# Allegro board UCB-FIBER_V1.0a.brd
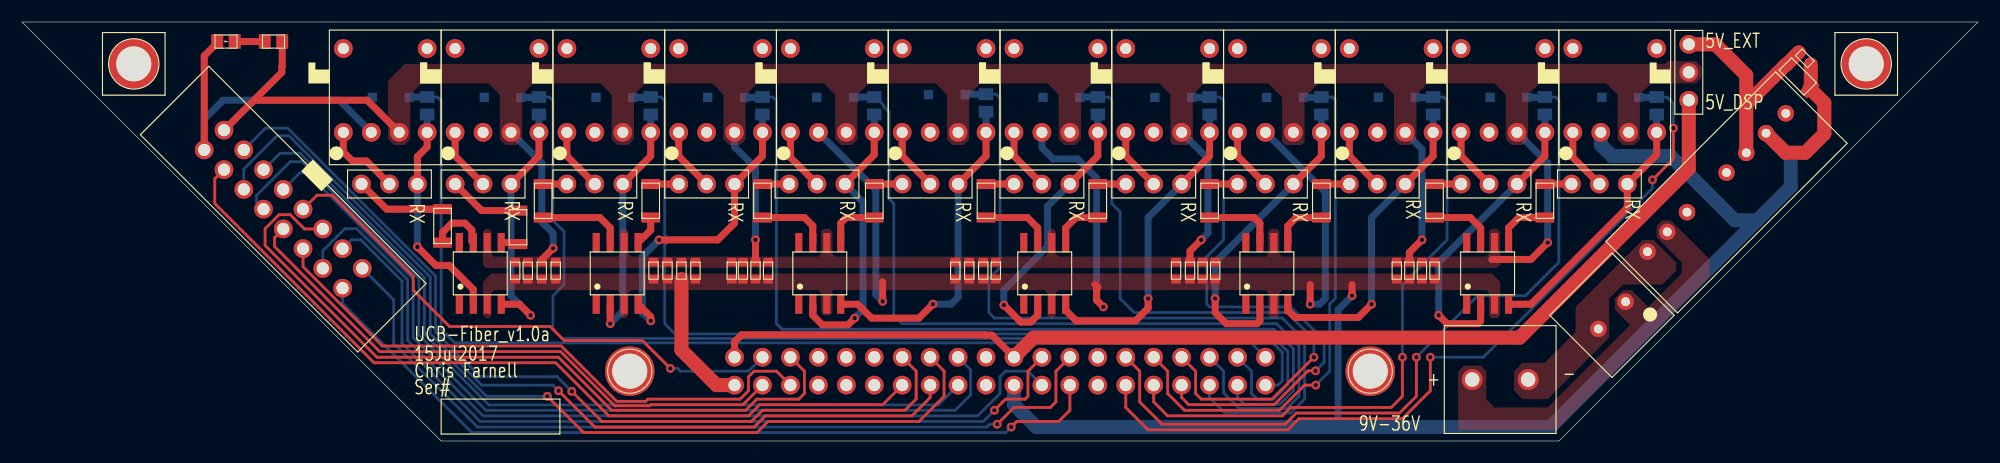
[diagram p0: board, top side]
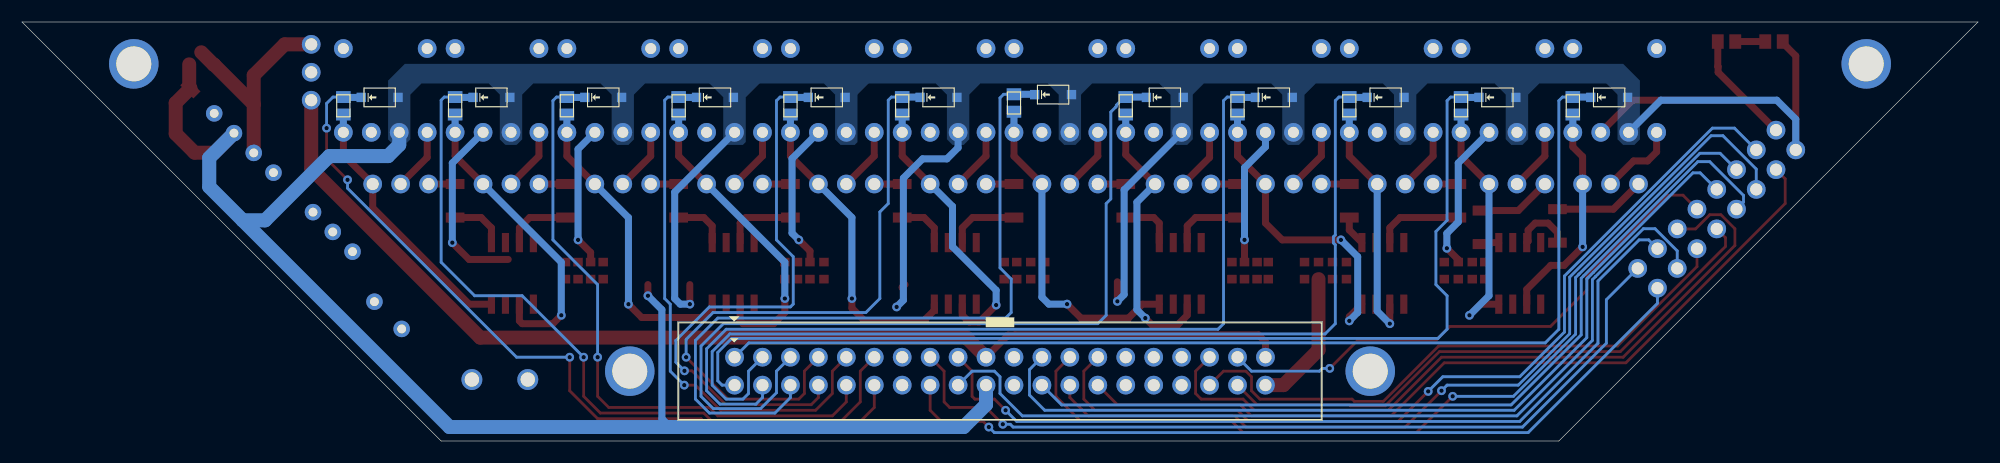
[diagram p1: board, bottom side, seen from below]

Outline 177.8 x 38.1 mm; copper layers: TOP, BOTTOM. Coordinates in mm from the lower left corner of the outline.
Outline path: 0,38.1 38.1,0 139.7,0 177.8,38.1 0,38.1

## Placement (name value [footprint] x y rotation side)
C1  0.1uF  [C_0603]  44.83 15.49 90 top
C2  0.1uF  [C_0603]  45.97 15.49 90 top
C3  0.1uF  [C_0603]  57.4 15.49 90 top
C4  0.1uF  [C_0603]  58.67 15.49 90 top
C5  0.1uF  [C_0603]  66.67 15.49 90 top
C6  0.1uF  [C_0603]  67.82 15.49 90 top
C7  0.1uF  [C_0603]  87.38 15.49 90 top
C8  0.1uF  [C_0603]  88.52 15.49 90 top
C9  0.1uF  [C_0603]  107.31 15.49 90 top
C10  0.1uF  [C_0603]  108.46 15.49 90 top
C11  0.1uF  [C_0603]  127.25 15.49 90 top
C12  0.1uF  [C_0603]  128.4 15.49 90 top
C13  0.1uF  [C_0603]  47.24 15.49 270 top
C14  0.1uF  [C_0603]  59.94 15.49 270 top
C15  0.1uF  [C_0603]  65.53 15.49 270 top
C16  0.1uF  [C_0603]  86.11 15.49 270 top
C17  0.1uF  [C_0603]  106.17 15.49 270 top
C18  0.1uF  [C_0603]  126.11 15.49 270 top
C19  1uF  [C_0603]  48.51 15.49 270 top
C20  1uF  [C_0603]  61.21 15.49 270 top
C21  1uF  [C_0603]  64.52 15.49 270 top
C22  1uF  [C_0603]  84.84 15.49 270 top
C23  1uF  [C_0603]  104.9 15.49 270 top
C24  1uF  [C_0603]  124.97 15.49 270 top
C25  100uF  [UVZ1H101MPD]  144.53 11.43 225 top
C26  10uF  [C_1206]  161.42 33.15 315 top
C27  0.1uF  [C_0603]  162.05 34.8 315 top
D1  BZT52C3V3-7-F  [SOD-123]  33.53 31.24 180 bottom
D2  BZT52C3V3-7-F  [SOD-123]  43.69 31.24 180 bottom
D3  BZT52C3V3-7-F  [SOD-123]  53.85 31.24 180 bottom
D4  BZT52C3V3-7-F  [SOD-123]  64.01 31.24 180 bottom
D5  BZT52C3V3-7-F  [SOD-123]  73.91 31.24 180 bottom
D6  BZT52C3V3-7-F  [SOD-123]  84.07 31.5 180 bottom
D7  BZT52C3V3-7-F  [SOD-123]  94.49 31.24 180 bottom
D8  BZT52C3V3-7-F  [SOD-123]  104.65 31.24 180 bottom
D9  BZT52C3V3-7-F  [SOD-123]  114.81 31.24 180 bottom
D10  BZT52C3V3-7-F  [SOD-123]  124.97 31.24 180 bottom
D11  BZT52C3V3-7-F  [SOD-123]  135.13 31.24 180 bottom
D12  BZT52C3V3-7-F  [SOD-123]  145.29 31.24 180 bottom
D13  LED-G  [LED_0805-GREEN]  18.54 36.32 0 top
J1  SFH11-PBPC-D20-ST-BK  [40-IDC-F_MNT]  88.9 6.35 270 bottom
J2  AWHW 16G-0202-T  [16-IDC-M]  23.75 21.08 225 top
J3  -  [1715721]  134.37 5.59 90 top
JP1  JP3  [J_1X3]  33.4 23.37 90 top
JP2  JP3  [J_1X3]  41.91 23.37 90 top
JP3  JP3  [J_1X3]  52.07 23.37 90 top
JP4  JP3  [J_1X3]  62.23 23.37 90 top
JP5  JP3  [J_1X3]  72.26 23.37 90 top
JP6  JP3  [J_1X3]  82.55 23.37 90 top
JP7  JP3  [J_1X3]  92.71 23.37 90 top
JP8  JP3  [J_1X3]  102.87 23.37 90 top
JP9  JP3  [J_1X3]  113.03 23.37 90 top
JP10  JP3  [J_1X3]  123.19 23.37 90 top
JP11  JP3  [J_1X3]  133.35 23.37 90 top
JP12  JP3  [J_1X3]  143.38 23.37 90 top
JP13  JP3  [J_1X3]  151.51 33.53 180 top
MECH1  Mech_Hole  [4-40_SCREW]  10.16 34.29 0 top
MECH2  Mech_Hole  [4-40_SCREW]  167.64 34.29 0 top
PM1  EC4SAW-24S05N  [SIP-8]  154.94 22.61 135 top
R1  51  [R_1206]  38.23 19.56 90 top
R2  51  [R_1206]  45.09 19.43 90 top
R3  51  [R_1206]  47.37 21.84 90 top
R4  51  [R_1206]  57.15 21.84 90 top
R5  51  [R_1206]  67.31 21.84 90 top
R6  51  [R_1206]  77.47 21.84 90 top
R7  51  [R_1206]  87.63 21.84 90 top
R8  51  [R_1206]  97.79 21.84 90 top
R9  51  [R_1206]  107.95 21.84 90 top
R10  51  [R_1206]  118.11 21.84 90 top
R11  51  [R_1206]  128.4 21.84 90 top
R12  51  [R_1206]  138.43 21.84 90 top
R13  470  [R_0805]  36.83 30.48 270 bottom
R14  470  [R_0805]  46.99 30.48 270 bottom
R15  470  [R_0805]  57.15 30.48 270 bottom
R16  470  [R_0805]  67.31 30.48 270 bottom
R17  470  [R_0805]  77.47 30.48 270 bottom
R18  470  [R_0805]  87.63 30.73 270 bottom
R19  470  [R_0805]  97.79 30.48 270 bottom
R20  470  [R_0805]  107.95 30.48 270 bottom
R21  470  [R_0805]  118.11 30.48 270 bottom
R22  470  [R_0805]  128.27 30.48 270 bottom
R23  470  [R_0805]  138.43 30.48 270 bottom
R24  470  [R_0805]  148.59 30.48 270 bottom
R25  330  [R_0805]  22.86 36.32 180 top
U1  HFBR-X521Z  [HFBR-0500Z]  33.02 31.24 90 top
U2  HFBR-X521Z  [HFBR-0500Z]  43.18 31.24 90 top
U3  HFBR-X521Z  [HFBR-0500Z]  53.34 31.24 90 top
U4  HFBR-X521Z  [HFBR-0500Z]  63.5 31.24 90 top
U5  HFBR-X521Z  [HFBR-0500Z]  73.66 31.24 90 top
U6  HFBR-X521Z  [HFBR-0500Z]  83.82 31.24 90 top
U7  HFBR-X521Z  [HFBR-0500Z]  93.98 31.24 90 top
U8  HFBR-X521Z  [HFBR-0500Z]  104.14 31.24 90 top
U9  HFBR-X521Z  [HFBR-0500Z]  114.3 31.24 90 top
U10  HFBR-X521Z  [HFBR-0500Z]  124.46 31.24 90 top
U11  HFBR-X521Z  [HFBR-0500Z]  134.62 31.24 90 top
U12  HFBR-X521Z  [HFBR-0500Z]  144.78 31.24 90 top
U13  TC427COA  [8-SOIC]  41.66 15.24 90 top
U14  TC427COA  [8-SOIC]  54.1 15.24 90 top
U15  TC427COA  [8-SOIC]  72.52 15.24 90 top
U16  TC427COA  [8-SOIC]  92.96 15.24 90 top
U17  TC427COA  [8-SOIC]  113.16 15.24 90 top
U18  TC427COA  [8-SOIC]  133.22 15.24 90 top

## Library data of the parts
C1-C24 C26 C27 = CAP NP
C25 = CAP P
D1-D12 = D-Zener
D13 = LED
J1 = Header_2x20
J2 = Header_2x8
J3 = Connector-2
JP1-JP13 = JP3
MECH1 MECH2 = Mech_Hole
PM1 = EC4SA
R1-R25 = R-Standard
U1-U12 = HFBR-X521Z
U13-U18 = TC427COA

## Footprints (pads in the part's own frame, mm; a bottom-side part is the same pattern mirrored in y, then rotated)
4-40_SCREW
  round 4.5 hole 3.175: 1(0,0)
8-SOIC
  rect 1.75x0.65 smd: 1(-2.8,1.905) 2(-2.8,0.635) 3(-2.8,-0.635) 4(-2.8,-1.905) 5(2.8,-1.905) 6(2.8,-0.635) 7(2.8,0.635) 8(2.8,1.905)
16-IDC-M
  round 1.7 hole 1.1: 1(-1.27,8.89) 2(1.27,8.89) 3(-1.27,6.35) 4(1.27,6.35) 5(-1.27,3.81) 6(1.27,3.81) 7(-1.27,1.27) 8(1.27,1.27) 9(-1.27,-1.27) 10(1.27,-1.27) 11(-1.27,-3.81) 12(1.27,-3.81) 13(-1.27,-6.35) 14(1.27,-6.35) 15(-1.27,-8.89) 16(1.27,-8.89)
40-IDC-F_MNT
  round 4.5 hole 3.175: (0,-33.655) (0,33.655)
  round 1.7 hole 1.1: 1(-1.27,-24.13) 2(1.27,-24.13) 3(-1.27,-21.59) 4(1.27,-21.59) 5(-1.27,-19.05) 6(1.27,-19.05) 7(-1.27,-16.51) 8(1.27,-16.51) 9(-1.27,-13.97) 10(1.27,-13.97) 11(-1.27,-11.43) 12(1.27,-11.43) 13(-1.27,-8.89) 14(1.27,-8.89) 15(-1.27,-6.35) 16(1.27,-6.35) 17(-1.27,-3.81) 18(1.27,-3.81) 19(-1.27,-1.27) 20(1.27,-1.27) 21(-1.27,1.27) 22(1.27,1.27) 23(-1.27,3.81) 24(1.27,3.81) 25(-1.27,6.35) 26(1.27,6.35) 27(-1.27,8.89) 28(1.27,8.89) 29(-1.27,11.43) 30(1.27,11.43) 31(-1.27,13.97) 32(1.27,13.97) 33(-1.27,16.51) 34(1.27,16.51) 35(-1.27,19.05) 36(1.27,19.05) 37(-1.27,21.59) 38(1.27,21.59) 39(-1.27,24.13) 40(1.27,24.13)
1715721
  round 1.9 hole 1.3: 1(0,2.54) 2(0,-2.54)
C_0603
  rect 0.787x0.864 smd: 1(-0.775,0) 2(0.775,0)
C_1206
  rect 0.914x1.702 smd: 1(-1.524,0) 2(1.524,0)
HFBR-0500Z
  round 1.7 hole 1: (4.445,3.81) (4.445,-3.81) 1(-3.175,3.81) 2(-3.175,1.27) 3(-3.175,-1.27) 4(-3.175,-3.81)
J_1X3
  round 1.7 hole 1.1: 1(0,2.54) 2(0,0) 3(0,-2.54)
LED_0805-GREEN
  rect 1.08x1.321 smd: 1(-0.794,0) 2(0.794,0)
R_0805
  rect 1.08x1.321 smd: 1(-0.794,0) 2(0.794,0)
R_1206
  rect 0.914x1.702 smd: 1(-1.524,0) 2(1.524,0)
SIP-8
  round 1.5 hole 0.8: 1(1.27,8.89) 2(1.27,6.35) 3(1.27,3.81) 5(1.27,-1.27) 6(1.27,-3.81) 7(1.27,-6.35) 8(1.27,-8.89)
SOD-123
  rect 0.85x0.85 smd: 1(-1.675,0) 2(1.675,0)
UVZ1H101MPD
  round 1.5 hole 0.8: 1(-1.75,0) 2(1.75,0)

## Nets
5V: C1.2 C2.2 C3.2 C4.2 C5.2 C6.2 C7.2 C8.2 C9.2 C10.2 C11.2 C12.2 C13.1 C14.1 C15.1 C16.1 C17.1 C18.1 C19.1 C20.1 C21.1 C22.1 C23.1 C24.1 J2.15 JP13.2 R25.1 U1.3 U2.3 U3.3 U4.3 U5.3 U6.3 U7.3 U8.3 U9.3 U10.3 U11.3 U12.3 U13.6(VDD) U14.6(VDD) U15.6(VDD) U16.6(VDD) U17.6(VDD) U18.6(VDD)
5V_DSP: J1.19 J1.39 JP13.1
5V_EXT: C26.1 C27.1 JP13.3 PM1.6(+VO)
GND: C1.1 C2.1 C3.1 C4.1 C5.1 C6.1 C7.1 C8.1 C9.1 C10.1 C11.1 C12.1 C13.2 C14.2 C15.2 C16.2 C17.2 C18.2 C19.2 C20.2 C21.2 C22.2 C23.2 C24.2 C26.2 C27.2 D1.2 D2.2 D3.2 D4.2 D5.2 D6.2 D7.2 D8.2 D9.2 D10.2 D11.2 D12.2 D13.1(CATHODE) J1.20 J1.40 J2.16 PM1.7(-VO) U1.2 U2.2 U3.2 U4.2 U5.2 U6.2 U7.2 U8.2 U9.2 U10.2 U11.2 U12.2 U13.3(GND) U14.3(GND) U15.3(GND) U16.3(GND) U17.3(GND) U18.3(GND)
ADC_0: J1.15 J2.1
ADC_1: J1.16 J2.2
ADC_2: J1.17 J2.3
ADC_3: J1.18 J2.4
ADC_4: J1.35 J2.5
ADC_5: J1.36 J2.6
ADC_6: J1.37 J2.7
ADC_7: J1.38 J2.8
IO_1: J1.23 J2.9
IO_2: J1.24 J2.10
IO_3: J1.25 J2.11
IO_4: J1.26 J2.12
IO_5: J1.27 J2.13
IO_6: J1.28 J2.14
TX/RX-3V3_1: D1.1 J1.1 R13.1
TX/RX-3V3_2: D2.1 J1.2 R14.1
TX/RX-3V3_3: D3.1 J1.3 R15.1
TX/RX-3V3_4: D4.1 J1.4 R16.1
TX/RX-3V3_5: D5.1 J1.5 R17.1
TX/RX-3V3_6: D6.1 J1.6 R18.1
TX/RX-3V3_7: D7.1 J1.7 R19.1
TX/RX-3V3_8: D8.1 J1.8 R20.1
TX/RX-3V3_9: D9.1 J1.9 R21.1
TX/RX-3V3_10: D10.1 J1.10 R22.1
TX/RX-3V3_11: D11.1 J1.11 R23.1
TX/RX-3V3_12: D12.1 J1.12 R24.1
TX/RX_1: JP1.3 R13.2 U1.4 U13.2(IN_A)
TX/RX_2: JP2.3 R14.2 U2.4 U13.4(IN_B)
TX/RX_3: JP3.3 R15.2 U3.4 U14.2(IN_A)
TX/RX_4: JP4.3 R16.2 U4.4 U14.4(IN_B)
TX/RX_5: JP5.3 R17.2 U5.4 U15.2(IN_A)
TX/RX_6: JP6.3 R18.2 U6.4 U15.4(IN_B)
TX/RX_7: JP7.3 R19.2 U7.4 U16.2(IN_A)
TX/RX_8: JP8.3 R20.2 U8.4 U16.4(IN_B)
TX/RX_9: JP9.3 R21.2 U9.4 U17.2(IN_A)
TX/RX_10: JP10.3 R22.2 U10.4 U17.4(IN_B)
TX/RX_11: JP11.3 R23.2 U11.4 U18.2(IN_A)
TX/RX_12: JP12.3 R24.2 U12.4 U18.4(IN_B)
TXD_1: R1.1 U13.7(OUT_A)
TXD_2: R2.1 U13.5(OUT_B)
TXD_3: R3.1 U14.7(OUT_A)
TXD_4: R4.1 U14.5(OUT_B)
TXD_5: R5.1 U15.7(OUT_A)
TXD_6: R6.1 U15.5(OUT_B)
TXD_7: R7.1 U16.7(OUT_A)
TXD_8: R8.1 U16.5(OUT_B)
TXD_9: R9.1 U17.7(OUT_A)
TXD_10: R10.1 U17.5(OUT_B)
TXD_11: R11.1 U18.7(OUT_A)
TXD_12: R12.1 U18.5(OUT_B)
N01550: JP1.2 U1.1
N02084: JP1.1 R1.2
N02867: JP2.2 U2.1
N02957: JP2.1 R2.2
N03301: JP3.2 U3.1
N03391: JP3.1 R3.2
N03756: JP4.2 U4.1
N03846: JP4.1 R4.2
N04236: JP5.2 U5.1
N04326: JP5.1 R5.2
N05708: JP6.2 U6.1
N05798: JP6.1 R6.2
N05904: JP7.2 U7.1
N05978: JP7.1 R7.2
N06100: JP8.2 U8.1
N06174: JP8.1 R8.2
N06296: JP9.2 U9.1
N06386: JP9.1 R9.2
N06492: JP10.2 U10.1
N06582: JP10.1 R10.2
N07286: JP11.2 U11.1
N07376: JP11.1 R11.2
N07482: JP12.2 U12.1
N07572: JP12.1 R12.2
N25651: C25.1 J3.1(P1) PM1.2(+VIN)
N25663: C25.2 J3.2(P2) PM1.1(-VIN)
N45703: D13.2(ANODE) R25.2

Pads without a net: J1 13 14 21 22 29 30 31 32 33 34; MECH1 1; MECH2 1; PM1 3 5 8; U13 1 8; U14 1 8; U15 1 8; U16 1 8; U17 1 8; U18 1 8

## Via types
v1: diameter 0.8, hole 0.4, TOP to BOTTOM, 36 vias

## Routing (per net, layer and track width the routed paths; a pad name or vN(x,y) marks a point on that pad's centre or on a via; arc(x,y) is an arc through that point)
5V: length 94.3
  TOP w0.635: 21.08,30.99 23.62,33.53 23.62,34.04 23.65,34.07 R25.1 ; 21.08,30.99 31.37,30.99 U1.3 ; 21.08,30.99 J2.15 ; v1(48.28,17.53) 47.24,16.49 C13.1 ; v1(127.25,18.29) 126.11,17.14 C18.1 ; v1(138.68,18.03) 137.16,16.51 133.6,16.51 ; C17.1 106.17,17.27 v1(107.19,18.29) ; C5.2 v1(66.67,18.29)
  BOTTOM w0.635: U2.3 47.24,25.27 47.24,19.92 48.28,18.88 v1(48.28,17.53) ; U4.3 64.77,26.75 66.67,24.84 v1(66.67,18.29) ; v1(107.19,18.29) 107.8,18.9 107.8,25.67 U8.3 ; U10.3 127.25,26.54 v1(127.25,18.29) ; U11.3 138.68,25.27 v1(138.68,18.03)
5V_DSP: length 102.6
  TOP w0.635: J1.39 64.77,9.02 65.41,9.65 87.53,9.65 87.56,9.63 88.16,9.63 J1.19
  TOP w1.27: J1.19 91.95,9.4 136.14,9.4 151.51,24.77 JP13.1
5V_EXT: length 20.2
  TOP w1.27: 156.74,30.62 PM1.6 ; 156.74,30.62 C26.1 160.38,34.22 C27.1 ; 156.74,30.62 156.74,33.26 153.92,36.07 JP13.3
GND: length 238.8
  TOP w0.635: 120.9,14.22 v1(120.9,13.21) ; D13.1 17.75,36.2 16.56,35.02 J2.16 ; 117.09,14.22 v1(117.09,12.45) ; 97.54,14.22 97.79,13.97 97.68,13.86 97.68,12.81 v1(98.3,12.19) ; 78.23,14.48 v1(78.23,12.7)
  TOP w1.27: C27.2 162.6,32.17 C26.2 163.83,30.73 163.83,27.94 162.11,26.22 160.31,26.22 PM1.7 ; C14.2 59.94,8.27 63.13,5.08 J1.40
  BOTTOM w0.635: U5.2 77.62,22.84 77.62,13.32 v1(78.23,12.7) ; U9.2 118.47,22.63 118.47,12.95 117.96,12.45 v1(117.09,12.45) ; 118.87,1.27 119.63,2.03 119.63,11.94 v1(120.9,13.21) ; J2.16 16.56,29.26 18.29,30.99 28.83,30.99 U1.2 ; v1(98.3,12.19) 97.68,12.81 97.68,23.91 95.93,25.65 93.73,25.65 92.71,26.67 U7.2
  BOTTOM w1.27: 157.73,20.07 138.94,1.27 92.2,1.27 90.17,3.3 J1.20 ; 157.73,20.07 155.7,20.07 149.86,25.91 144.53,25.91 143.51,26.92 U12.2 ; 157.73,20.07 160.78,23.11 160.78,25.74 PM1.7
ADC_0: length 76.9
  TOP w0.254: J1.15 93.98,6.35 93.98,3.56 93.47,3.05 90.17,3.05 v1(88.65,1.52)
  BOTTOM w0.254: v1(88.65,1.52) 87.97,1.52 87.71,1.27 41.4,1.27 33.78,8.89 33.78,12.85 J2.1
ADC_1: length 75.5
  TOP w0.254: J1.16 95.25,2.79 94.23,1.78 90.42,1.78 v1(89.92,1.27)
  BOTTOM w0.254: J2.2 29.14,12.52 40.89,0.76 89.41,0.76 v1(89.92,1.27)
ADC_2: length 77.8
  TOP w0.254: v1(88.39,2.79) 89.41,3.81 91.19,3.81 91.44,4.06 91.44,6.35 J1.17
  BOTTOM w0.254: J2.3 29.94,18.29 30.8,18.29 34.54,14.54 34.54,8.89 41.66,1.78 87.38,1.78 v1(88.39,2.79)
ADC_3: length 81.2
  BOTTOM w0.254: J2.4 27.34,17.29 29.35,19.3 30.41,19.3 34.78,14.94 35.05,14.67 35.05,9.14 41.91,2.29 86.87,2.29 88.9,4.32 88.9,5.84 89.41,6.35 91.44,6.35 J1.18
ADC_4: length 67.5
  TOP w0.254: J1.35 71.12,6.35 71.12,4.32 70.61,3.81 66.8,3.81 65.79,2.79 53.59,2.79 48.77,7.62 32.26,7.62 22.1,17.78 22.1,19.3 23.37,20.57 24.38,20.57 25.67,19.29 J2.5
ADC_5: length 53.4
  TOP w0.254: J2.6 25.55,15.86 32.77,8.64 49.02,8.64 54.05,3.61 56.69,3.61 56.9,3.81 65.28,3.81 66.04,4.57 66.04,5.84 66.55,6.35 68.58,6.35 J1.36
ADC_6: length 50.2
  TOP w0.254: J2.7 26.82,22.35 28.19,22.35 35.56,14.99 35.56,13.72 38.86,10.41 48.01,10.41 49.28,9.14 56.39,9.14 v1(58.93,6.6)
  BOTTOM w0.254: v1(58.93,6.6) 59.61,6.6 59.86,6.35 66.04,6.35 J1.37
ADC_7: length 53.1
  TOP w0.254: J2.8 22.95,18.49 22.95,17.69 32.51,8.13 48.95,8.13 53.88,3.2 57.05,3.2 57.15,3.3 65.53,3.3 J1.38
IO_1: length 79.6
  BOTTOM w0.254: J2.9 25.25,24.38 25.91,24.38 34.94,15.35 35.46,14.83 35.56,14.73 35.56,9.4 42.16,2.79 84.84,2.79 86.22,4.18 86.22,6.49 J1.23
IO_2: length 79.5
  BOTTOM w0.254: J2.10 21.32,21.72 21.32,22.33 24.38,25.4 25.47,25.4 35.86,15 36.07,14.8 36.07,9.65 42.44,3.28 83.29,3.28 J1.24
IO_3: length 81.5
  TOP w0.254: v1(47.75,4.06) 51.05,0.76 66.8,0.76 67.82,1.78 81.53,1.78 83.82,4.06 83.82,6.35 J1.25
  BOTTOM w0.254: J2.11 23.44,26.16 25.28,26.16 36.27,15.17 36.58,14.87 36.58,9.72 42.23,4.06 v1(47.75,4.06)
IO_4: length 81.7
  TOP w0.254: v1(48.77,4.57) 52.07,1.27 66.55,1.27 67.56,2.29 80.89,2.29 82.55,3.95 J1.26
  BOTTOM w0.254: J2.12 20.16,24.73 23.19,27.76 24.26,27.76 37.12,14.9 37.12,9.75 41.79,5.08 48.26,5.08 v1(48.77,4.57)
IO_5: length 81.2
  TOP w0.254: J1.27 81.28,6.35 81.28,3.81 80.26,2.79 67.31,2.79 66.29,1.78 52.71,1.78 v1(49.98,4.51)
  BOTTOM w0.254: v1(49.98,4.51) 48.65,5.84 41.66,5.84 37.59,9.91 37.59,15 24.14,28.45 22.13,28.45 J2.13
IO_6: length 75.1
  TOP w0.254: J2.14 17.53,23.84 17.53,21.59 32,7.11 48.51,7.11 53.34,2.29 66.04,2.29 67.06,3.3 78.23,3.3 J1.28
TX/RX-3V3_1: length 99.8
  BOTTOM w0.254: R13.1 37.77,31.27 38.1,30.94 38.1,10.16 39.34,8.92 111.73,8.92 J1.1
  BOTTOM w0.635: D1.1 35.23,31.27 R13.1
TX/RX-3V3_2: length 96.1
  BOTTOM w0.254: J1.2 114.16,5.08 114.55,5.47 114.55,8.06 113.29,9.33 49.09,9.33 48.26,10.16 48.26,13.21 49.28,14.22 49.28,19.05 48.26,20.07 48.26,30.94 47.93,31.27 R14.1
  BOTTOM w0.635: D2.1 46.96,31.24 R14.1
TX/RX-3V3_3: length 92.1
  BOTTOM w0.254: R15.1 58.09,31.27 58.42,30.94 58.42,18.74 58.59,18.57 58.59,18.01 58.42,17.83 58.42,10.67 59.35,9.73 113.46,9.73 115.06,8.13 115.06,5.08 113.79,3.81 112.27,3.81 111.76,4.32 111.76,6.35 J1.3
  BOTTOM w0.635: R15.1 57.12,31.24 D3.1
TX/RX-3V3_4: length 82
  BOTTOM w0.254: J1.4 110.49,3.95 111.09,3.35 114.35,3.35 115.57,4.57 115.57,8.38 113.79,10.16 69.09,10.16 68.58,10.67 68.58,30.94 68.25,31.27 R16.1
  BOTTOM w0.635: D4.1 67.28,31.24 R16.1
TX/RX-3V3_5: length 76.8
  BOTTOM w0.254: J1.5 109.22,6.35 109.22,4.38 110.66,2.95 114.96,2.95 116.08,4.06 116.08,8.64 114.05,10.67 80.01,10.67 79.25,11.43 79.25,21.59 78.83,22.01 78.83,29.92 78.41,30.33 78.41,30.34 78.33,30.42 78.33,30.54 77.59,31.27 R17.1
  BOTTOM w0.635: D5.1 75.62,31.27 R17.1
TX/RX-3V3_6: length 69.2
  BOTTOM w0.254: R18.1 88.57,31.53 88.9,31.2 88.9,15.75 87.88,14.73 87.88,11.68 88.39,11.18 114.55,11.18 116.59,9.14 116.59,3.81 115.32,2.54 109.36,2.54 107.95,3.95 J1.6
  BOTTOM w0.635: D6.1 85.78,31.53 R18.1
TX/RX-3V3_7: length 58.5
  TOP w0.254: v1(117.43,7.62) 113.62,3.81 107.19,3.81 106.68,4.32 106.68,6.35 J1.7
  BOTTOM w0.254: v1(117.43,7.62) 117.43,9.23 114.98,11.68 101.09,11.68 99.82,12.95 99.82,20.83 99.06,21.59 99.06,30.99 98.77,31.27 R19.1
  BOTTOM w0.635: R19.1 96.19,31.27 D7.1
TX/RX-3V3_8: length 52.1
  TOP w0.254: v1(117.58,6.38) 116.9,6.38 113.82,3.3 106.06,3.3 105.41,3.95 J1.8
  BOTTOM w0.254: R20.1 108.89,31.27 109.22,30.94 109.22,18.29 107.7,16.76 107.7,12.45 107.95,12.19 115.32,12.19 118.36,9.14 118.36,7.16 v1(117.58,6.38)
  BOTTOM w0.635: R20.1 107.92,31.24 D8.1
TX/RX-3V3_9: length 48.5
  TOP w0.254: v1(117.6,5.08) 116.59,5.08 114.3,2.79 105.66,2.79 104.14,4.32 104.14,6.35 J1.9
  BOTTOM w0.254: v1(117.6,5.08) 118.87,6.35 118.87,12.45 119.38,12.95 119.38,30.99 119.09,31.27 R21.1
  BOTTOM w0.635: R21.1 118.08,31.24 D9.1
TX/RX-3V3_10: length 57
  TOP w0.254: v1(125.48,7.62) 125.48,4.06 124.46,3.05 115.32,3.05 114.55,2.29 104.14,2.29 102.87,3.56 J1.10
  BOTTOM w0.254: R22.1 129.21,31.27 129.54,30.94 129.54,18.29 125.48,14.22 v1(125.48,7.62)
  BOTTOM w0.635: R22.1 128.24,31.24 D10.1
TX/RX-3V3_11: length 69.5
  TOP w0.254: J1.11 101.6,6.35 101.6,3.56 103.63,1.52 114.81,1.52 115.82,2.54 125.22,2.54 126.75,4.06 v1(126.75,7.62)
  BOTTOM w0.254: R23.1 139.41,31.27 139.7,30.99 139.7,16.26 136.65,13.21 132.33,13.21 v1(126.75,7.62)
  BOTTOM w0.635: R23.1 138.4,31.24 D11.1
TX/RX-3V3_12: length 73.5
  TOP w0.254: v1(150.11,28.45) 150.11,25.65 v1(148.21,23.75) ; v1(128.02,7.62) 128.02,4.57 125.48,2.03 116.08,2.03 115.06,1.02 102.36,1.02 100.33,3.05 J1.12
  BOTTOM w0.254: R24.1 149.53,31.27 150.11,30.69 v1(150.11,28.45) ; v1(148.21,23.75) 148.21,22.99 132.84,7.62 v1(128.02,7.62)
  BOTTOM w0.635: R24.1 148.56,31.24 D12.1
TX/RX_1: length 20.4
  TOP w0.635: v1(35.94,17.65) 37.62,15.97 38.83,15.97 41.02,13.78 41.02,12.44 ; U1.4 36.83,26.75 35.94,25.86 JP1.3
  BOTTOM w0.635: JP1.3 v1(35.94,17.65) ; R13.2 U1.4
TX/RX_2: length 23.1
  TOP w0.635: U13.4 45.22,12.44 v1(46.23,11.43) ; U2.4 46.99,25.91 JP2.3
  BOTTOM w0.635: R14.2 U2.4 ; v1(46.23,11.43) 44.45,13.21 JP2.3
TX/RX_3: length 22.3
  TOP w0.635: U3.4 57.15,25.91 JP3.3 ; U14.2 v1(53.47,10.67)
  BOTTOM w0.635: JP3.3 54.61,11.81 v1(53.47,10.67) ; R15.2 U3.4
TX/RX_4: length 28.7
  TOP w0.635: U4.4 67.31,25.91 JP4.3 64.77,19.81 63.25,18.29 v1(57.91,18.29) ; v1(57.15,10.92) 57.15,11.3 U14.4
  BOTTOM w0.635: R16.2 U4.4 ; v1(57.15,10.92) 56.39,11.68 56.39,16.76 v1(57.91,18.29)
TX/RX_5: length 26
  TOP w0.635: U15.2 71.88,11.43 72.75,10.56 75.08,10.56 v1(75.69,11.18) ; U5.4 77.47,26.04 74.8,23.37
  BOTTOM w0.635: 74.8,23.37 76.45,21.72 76.45,11.94 v1(75.69,11.18) ; R17.2 U5.4
TX/RX_6: length 29.9
  TOP w0.635: U15.4 75.95,12.44 77.22,11.18 81.53,11.18 v1(82.8,12.45) ; JP6.3 87.63,25.91 U6.4
  BOTTOM w0.635: JP6.3 85.09,13.08 84.45,12.45 v1(82.8,12.45) ; U6.4 R18.2
TX/RX_7: length 25.8
  TOP w0.635: U7.4 97.79,25.91 JP7.3 ; v1(89.25,12.36) 90.8,10.81 91.69,10.81 92.33,11.45 U16.2
  BOTTOM w0.635: JP7.3 93.22,21.34 93.22,17.67 89.25,13.7 v1(89.25,12.36) ; U7.4 R19.2
TX/RX_8: length 28.8
  TOP w0.635: U8.4 107.95,25.91 JP8.3 ; U16.4 94.87,11.89 95.84,10.92 101.2,10.92 102.36,12.08 v1(102.36,12.95)
  BOTTOM w0.635: JP8.3 102.36,20.32 v1(102.36,12.95) ; U8.4 R20.2
TX/RX_9: length 28.1
  TOP w0.635: U17.2 112.52,10.92 112.27,10.67 109.47,10.67 108.46,11.68 v1(108.46,12.95) ; U9.4 118.11,25.91 JP9.3
  BOTTOM w0.635: JP9.3 108.46,16.26 v1(108.46,12.95) ; R21.2 U9.4
TX/RX_10: length 28.5
  TOP w0.635: v1(122.68,12.44) 121.47,11.23 115.72,11.23 115.06,11.89 U17.4 ; JP10.3 128.27,25.91 U10.4
  BOTTOM w0.635: R22.2 U10.4 ; JP10.3 122.68,20.31 v1(122.68,12.44)
TX/RX_11: length 28
  TOP w0.635: v1(128.78,11.43) 129.54,10.67 132.33,10.67 132.59,10.92 U18.2 ; U11.4 138.43,25.91 JP11.3
  BOTTOM w0.635: R23.2 U11.4 ; v1(128.78,11.43) 128.78,16.26 JP11.3
TX/RX_12: length 24
  TOP w0.635: U18.4 137.15,12.44 145.92,21.21 JP12.3 148.59,26.04 U12.4
  BOTTOM w0.635: R24.2 U12.4
TXD_1: length 5.4
  TOP w0.635: 38.23,18.03 38.23,18.96 39.08,19.81 40.26,19.81 40.89,19.18 40.89,18.17 41.02,18.04
TXD_2: length 1.6
  TOP w0.635: U13.5 44.95,18.04 R2.1
TXD_3: length 7.8
  TOP w0.635: U14.7 53.47,19.39 52.53,20.32 R3.1
TXD_4: length 2.8
  TOP w0.635: R4.1 57.15,19.18 U14.5
TXD_5: length 6.4
  TOP w0.635: U15.7 71.88,19.56 71.12,20.32 R5.1
TXD_6: length 5
  TOP w0.635: U15.5 74.42,19.81 74.93,20.32 R6.1
TXD_7: length 6.4
  TOP w0.635: U16.7 92.33,19.39 91.39,20.32 R7.1
TXD_8: length 4.7
  TOP w0.635: R8.1 95.8,20.32 94.87,19.39 U16.5
TXD_9: length 6.6
  TOP w0.635: R9.1 112.01,20.32 112.52,19.81 U17.7
TXD_10: length 4.9
  TOP w0.635: R10.1 115.82,20.32 115.06,19.56 U17.5
TXD_11: length 5.9
  TOP w0.635: U18.7 132.59,19.39 131.65,20.32 R11.1
TXD_12: length 5
  TOP w0.635: R12.1 136.06,20.32 135.13,19.39 U18.5
N01550: length 7.2
  TOP w0.635: U1.1 29.21,26.29 30.04,25.46 31.31,25.46 JP1.2
N02084: length 8.3
  TOP w0.635: JP1.1 33.15,21.08 R1.2
N02867: length 5.8
  TOP w0.635: U2.1 39.37,25.91 JP2.2
N02957: length 6.7
  TOP w0.635: JP2.1 41.78,20.95 R2.2
N03301: length 5.8
  TOP w0.635: U3.1 49.53,25.91 JP3.2
N03391: length 2.2
  TOP w0.635: JP3.1 R3.2
N03756: length 5.8
  TOP w0.635: JP4.2 59.69,25.91 U4.1
N03846: length 2.5
  TOP w0.635: R4.2 JP4.1
N04236: length 5.7
  TOP w0.635: JP5.2 69.85,25.78 U5.1
N04326: length 2.4
  TOP w0.635: 69.72,23.37 R5.2
N05708: length 5.8
  TOP w0.635: U6.1 80.01,25.91 JP6.2
N05798: length 2.5
  TOP w0.635: JP6.1 R6.2
N05904: length 5.8
  TOP w0.635: U7.1 90.17,25.91 JP7.2
N05978: length 2.5
  TOP w0.635: R7.2 JP7.1
N06100: length 5.8
  TOP w0.635: JP8.2 100.33,25.91 U8.1
N06174: length 2.5
  TOP w0.635: JP8.1 R8.2
N06296: length 5.8
  TOP w0.635: JP9.2 110.49,25.91 U9.1
N06386: length 2.5
  TOP w0.635: R9.2 JP9.1
N06492: length 5.8
  TOP w0.635: U10.1 120.65,25.91 JP10.2
N06582: length 2.5
  TOP w0.635: JP10.1 R10.2
N07286: length 5.8
  TOP w0.635: U11.1 130.81,25.91 JP11.2
N07376: length 2.4
  TOP w0.635: R11.2 JP11.1
N07482: length 5.7
  TOP w0.635: JP12.2 140.97,25.78 U12.1
N07572: length 2.4
  TOP w0.635: JP12.1 R12.2
N45703: length 2.7
  TOP w0.635: D13.2 R25.2

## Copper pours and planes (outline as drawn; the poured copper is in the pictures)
5V on TOP: 42.67,17.02 42.67,19.05 42.42,19.3 42.16,19.3 41.91,19.05 41.91,16 42.16,15.75 134.11,15.75 134.37,16 134.37,19.05 134.11,19.3 133.6,19.3 133.35,19.05 133.35,17.02 133.1,16.76 114.55,16.76 114.3,17.02 114.3,19.05 114.05,19.3 113.54,19.3 113.28,19.05 113.28,17.02 113.03,16.76 94.23,16.76 93.98,17.02 93.98,19.05 93.73,19.3 93.47,19.3 93.22,19.05 93.22,17.02 92.96,16.76 73.91,16.76 73.66,17.02 73.66,19.05 73.41,19.3 72.9,19.3 72.64,19.05 72.64,17.02 72.39,16.76 55.37,16.76 55.12,17.02 55.12,19.05 54.86,19.3 54.61,19.3 54.36,19.05 54.36,17.02 54.1,16.76 42.93,16.76
5V on TOP: outline of 102 points within 33.27,26.92 152.65,34.54
GND on TOP: 42.67,13.46 42.67,11.43 42.42,11.18 42.16,11.18 41.91,11.43 41.91,14.48 42.67,15.24 133.6,15.24 134.37,14.48 134.37,11.43 134.11,11.18 133.6,11.18 133.35,11.43 133.35,13.46 133.1,13.72 114.55,13.72 114.3,13.46 114.3,11.43 114.05,11.18 113.54,11.18 113.28,11.43 113.28,13.46 113.03,13.72 94.23,13.72 93.98,13.46 93.98,11.43 93.73,11.18 93.47,11.18 93.22,11.43 93.22,13.46 92.96,13.72 73.66,13.72 73.66,11.68 73.41,11.43 72.9,11.43 72.64,11.68 72.64,13.46 72.39,13.72 55.37,13.72 55.12,13.46 55.12,11.43 54.86,11.18 54.61,11.18 54.36,11.43 54.36,13.46 54.1,13.72 42.93,13.72
GND on BOTTOM: outline of 96 points within 30.73,26.92 144.53,34.29
N25651 on TOP: 147.32,9.4 144.78,11.94 144.78,12.95 145.54,13.72 146.3,13.72 148.84,11.18 148.84,10.41 147.83,9.4
N25651 on TOP: 148.59,19.56 149.1,20.07 149.86,20.07 153.42,16.51 153.42,14.99 139.45,1.02 130.56,1.02 130.56,6.35 131.06,6.86 132.59,6.86 133.1,6.35 133.1,3.81 133.86,3.05 138.68,3.05 150.88,15.24 150.88,16.26 148.59,18.54
N25663 on TOP: 136.4,7.11 135.64,6.35 135.64,4.57 136.4,3.81 138.68,3.81 144.27,9.4 144.27,12.95 145.54,14.22 149.1,14.22 150.37,15.49 150.37,16.26 148.34,18.29 147.32,18.29 141.22,12.19 141.22,9.91 138.43,7.11

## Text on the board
Ref Des/Silkscreen Top: UCB-Fiber_v1.0a | 15Jul2017 | Chris Farnell | Ser# | 9V-36V | + | - | 5V_EXT | 5V_DSP | RX
